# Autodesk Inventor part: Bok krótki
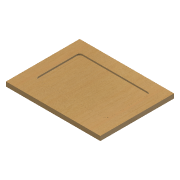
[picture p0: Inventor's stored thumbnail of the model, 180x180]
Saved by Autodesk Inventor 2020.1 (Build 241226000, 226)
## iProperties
Created: 2005-09
Part Number: Bok krótki
Document SubType Name: Modeling
Designer: F.Stasiak
Density: 1 g/cm^3
Material: Ogólny
Appearance: Sosna żółta — pełna — barwiona na jasno — niski połysk
Manager: www.cadconsulting.pl
Company: Fabian Stasiak CAD Consulting
Author: F.Stasiak
Subject: Zbiór ćwiczeń. Autodesk Inventor 2020. Kurs podstawowy
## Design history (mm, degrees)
sketch "Szkic1"
  geometry: L1 (-160, 250)-(160, 250); L2 (160, 250)-(160, 0); L3 (160, 0)-(-160, 0); L4 (-160, 0)-(-160, 250); 2 further points
  constraints: 8 end point, 2 parallel, 1 coincident, 1 horizontal, 1 midpoint, 1 perpendicular
  dimensions: "d0" = 320 distance of L2.end L3.end; "d1" = 250 distance of L1.end L2.end
extrude "Wyciągnięcie proste1" new body sketch "Szkic1" distance "d2" = 15; taper "d3" = 0 deg
sketch "Szkic2"
  geometry: L1 (160, 250)-(160, 0) reference; L2 (-160, 250)-(160, 250) reference; L3 (-160, 0)-(-160, 250) reference; L4 (160, 0)-(-160, 0) reference; L5 (-120, 210)-(120, 210); L6 (120, 210)-(120, 60); L7 (120, 60)-(-120, 60); L8 (-120, 60)-(-120, 210)
  constraints: 8 end point, 2 parallel, 1 horizontal, 1 perpendicular
  dimensions: "d4" = 40 distance between parallel lines of L2 L5; "d5" = 40 distance between parallel lines of L1 L6; "d6" = 40 distance between parallel lines of L3 L8; "d7" = 60 distance between parallel lines of L4 L7
extrude "Wyciągnięcie proste2" cut sketch "Szkic2" distance "d8" = 5; taper "d9" = 0 deg
fillet "Zaokrąglenie1" dims "d10" = 10
node "Bryła1"
node "Korpusy bryłowe"
node "Korpusy powierzchniowe"
node "Pętla rzutowana1"
